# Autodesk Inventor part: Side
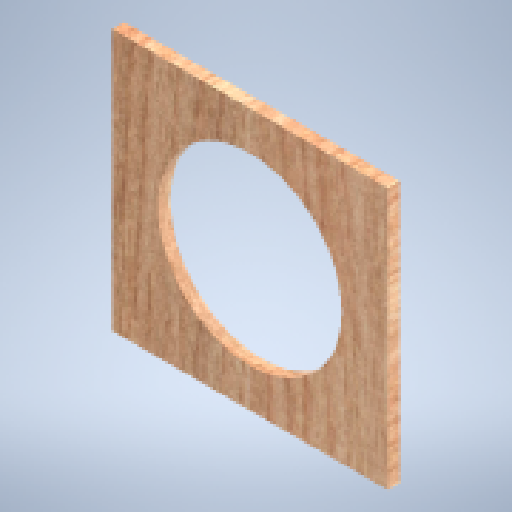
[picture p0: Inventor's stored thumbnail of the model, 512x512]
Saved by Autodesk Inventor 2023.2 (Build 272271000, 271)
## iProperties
Created: 2022-05
Part Number: Side
Material: Wood (Birch)
Document SubType Name: Modeling
Designer: elimb
Density: 0.55 g/cm^3
Appearance: Birch - Natural Polished
Author: elimb
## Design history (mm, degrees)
sketch "Sketch1"
  geometry: L1 (73.66, -69.85)-(-73.66, -69.85); L2 (-73.66, -69.85)-(-73.66, 69.85); L3 (-73.66, 69.85)-(73.66, 69.85); L4 (73.66, 69.85)-(73.66, -69.85); L5 (73.66, -69.85)-(-73.66, 69.85); L6 (-73.66, -69.85)-(73.66, 69.85); C1 r 49.124 at (0, 0); 1 further point
  constraints: 12 end point, 2 midpoint, 2 parallel, 1 centre point, 1 coincident, 1 horizontal, 1 perpendicular
  dimensions: "d0" = 98.2472 diameter of C1; "d2" = 139.7 distance of L1.end L2.end; "d5" = 147.32 distance of L1.start L1.end
extrude "Extrusion1" new body sketch "Sketch1" distance "d3" = 6.35; taper "d4" = 0 deg
body "Solid1"
